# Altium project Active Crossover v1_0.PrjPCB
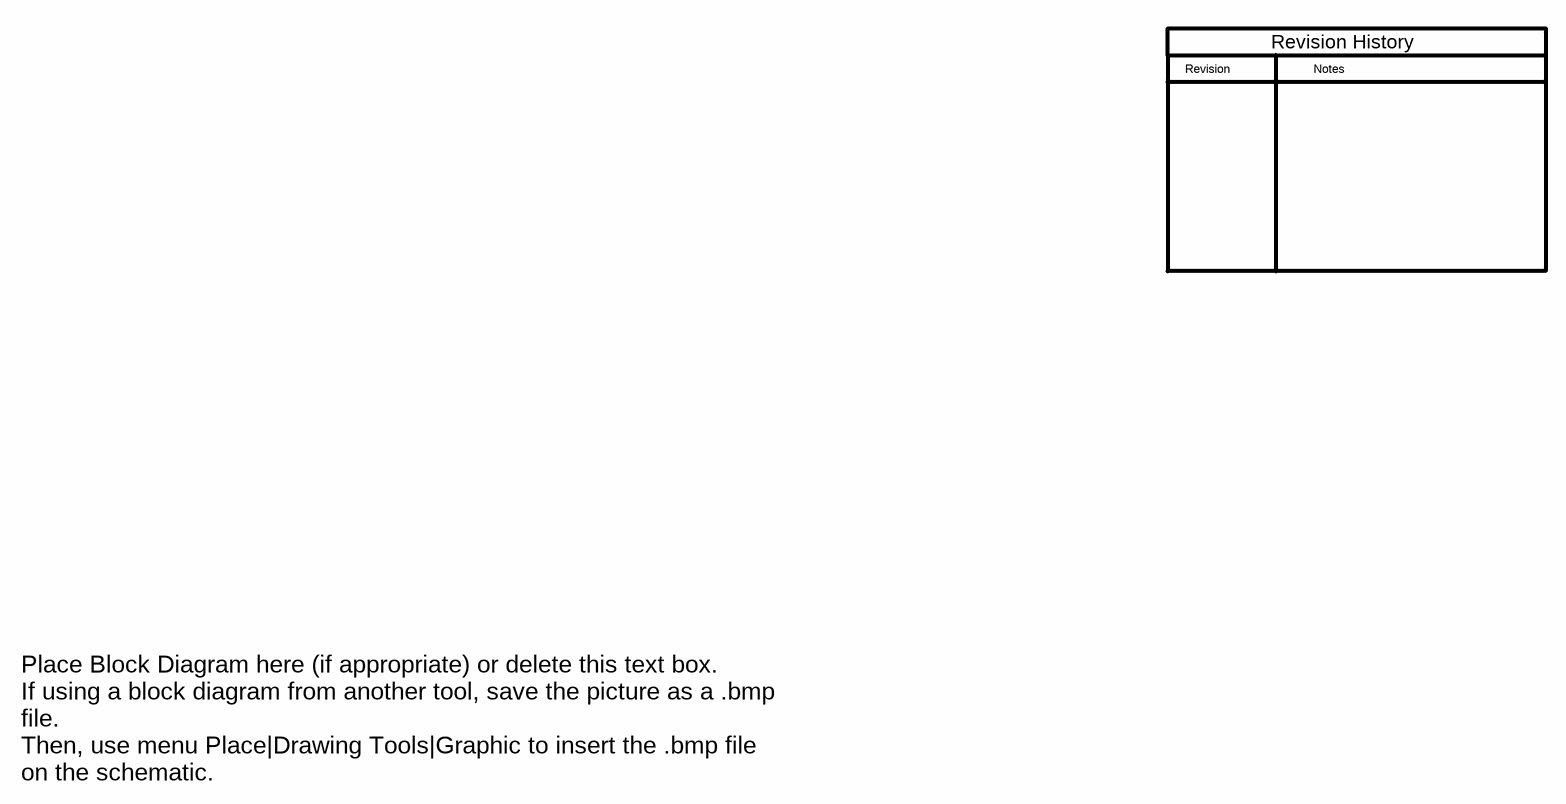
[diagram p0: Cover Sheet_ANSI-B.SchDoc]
TechSupport: http://www.ti.com/support; SCH_Rev: 1; PRJ_Title: Analog Active Loudspeaker Crossover; PRJ_Engineer: John Caldwell; PRJ_Customer: Public Release; PCB_Rev: 1; PCB_Layout: John Caldwell; CopyrightYear: 2013
2 sheets, 57 parts. Net scope: global (net labels, ports and power ports of the same name join across sheets).
Board file: Active Crossover v1_0.PcbDoc
Sheets:
  Cover Sheet_ANSI-B.SchDoc
  Schematic.SchDoc

## Sheet Cover Sheet_ANSI-B.SchDoc: ChangeMe
size 431 x 279 mm; Date: Not shown in title block; ApprovedBy: Not shown in title block; CheckedBy: Not shown in title block; Author: Not shown in title block; CompanyName: Not shown in title block; DrawnBy: Enter Full Name; Engineer: Not shown in title block; Organization: Not shown in title block; Address1: Not shown in title block; Address2: Not shown in title block; Address3: Not shown in title block; Address4: Not shown in title block; DocumentNumber: 1; Revision: Use project parameter SCH_Rev; SheetNumber: 1; SheetTotal: 3; PageSetup: Record=PageOptions|CenterHorizontal=True|CenterVertical=True|PrintScale=1.00|XCorrection=1.00|YCorrection=1.00|PrintKind=0|BorderSize=5000000|LeftOffset=0|BottomOffset=0|Orientation=2|PaperLength=1000|PaperWidth=1000|Scale=100|PaperSource=15|PrintQuality=600|MediaType=1|DitherType=10|PaperKind=Letter|PrintScaleMode=1

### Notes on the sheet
- Revision
- Notes
- Revision History
- Place Block Diagram here (if appropriate) or delete this text box.
  If using a block diagram from another tool, save the picture as a .bmp file.
  Then, use menu Place|Drawing Tools|Graphic to insert the .bmp file on the schematic.

## Sheet Schematic.SchDoc: ChangeMe
size 431 x 279 mm; Date: Not shown in title block; ApprovedBy: Not shown in title block; CheckedBy: Not shown in title block; Author: Not shown in title block; CompanyName: Not shown in title block; DrawnBy: Enter Full Name; Engineer: Not shown in title block; Organization: Not shown in title block; Address1: Not shown in title block; Address2: Not shown in title block; Address3: Not shown in title block; Address4: Not shown in title block; DocumentNumber: 2; Revision: Use project parameter SCH_Rev; SheetNumber: 2; SheetTotal: 3; PageSetup: Record=PageOptions|CenterHorizontal=True|CenterVertical=True|PrintScale=0.62|XCorrection=1.00|YCorrection=1.00|PrintKind=0|BorderSize=5000000|LeftOffset=0|BottomOffset=0|Orientation=2|PaperLength=1000|PaperWidth=1000|Scale=100|PaperSource=15|PrintQuality=600|MediaType=1|DitherType=10|PaperKind=Letter|PrintScaleMode=1
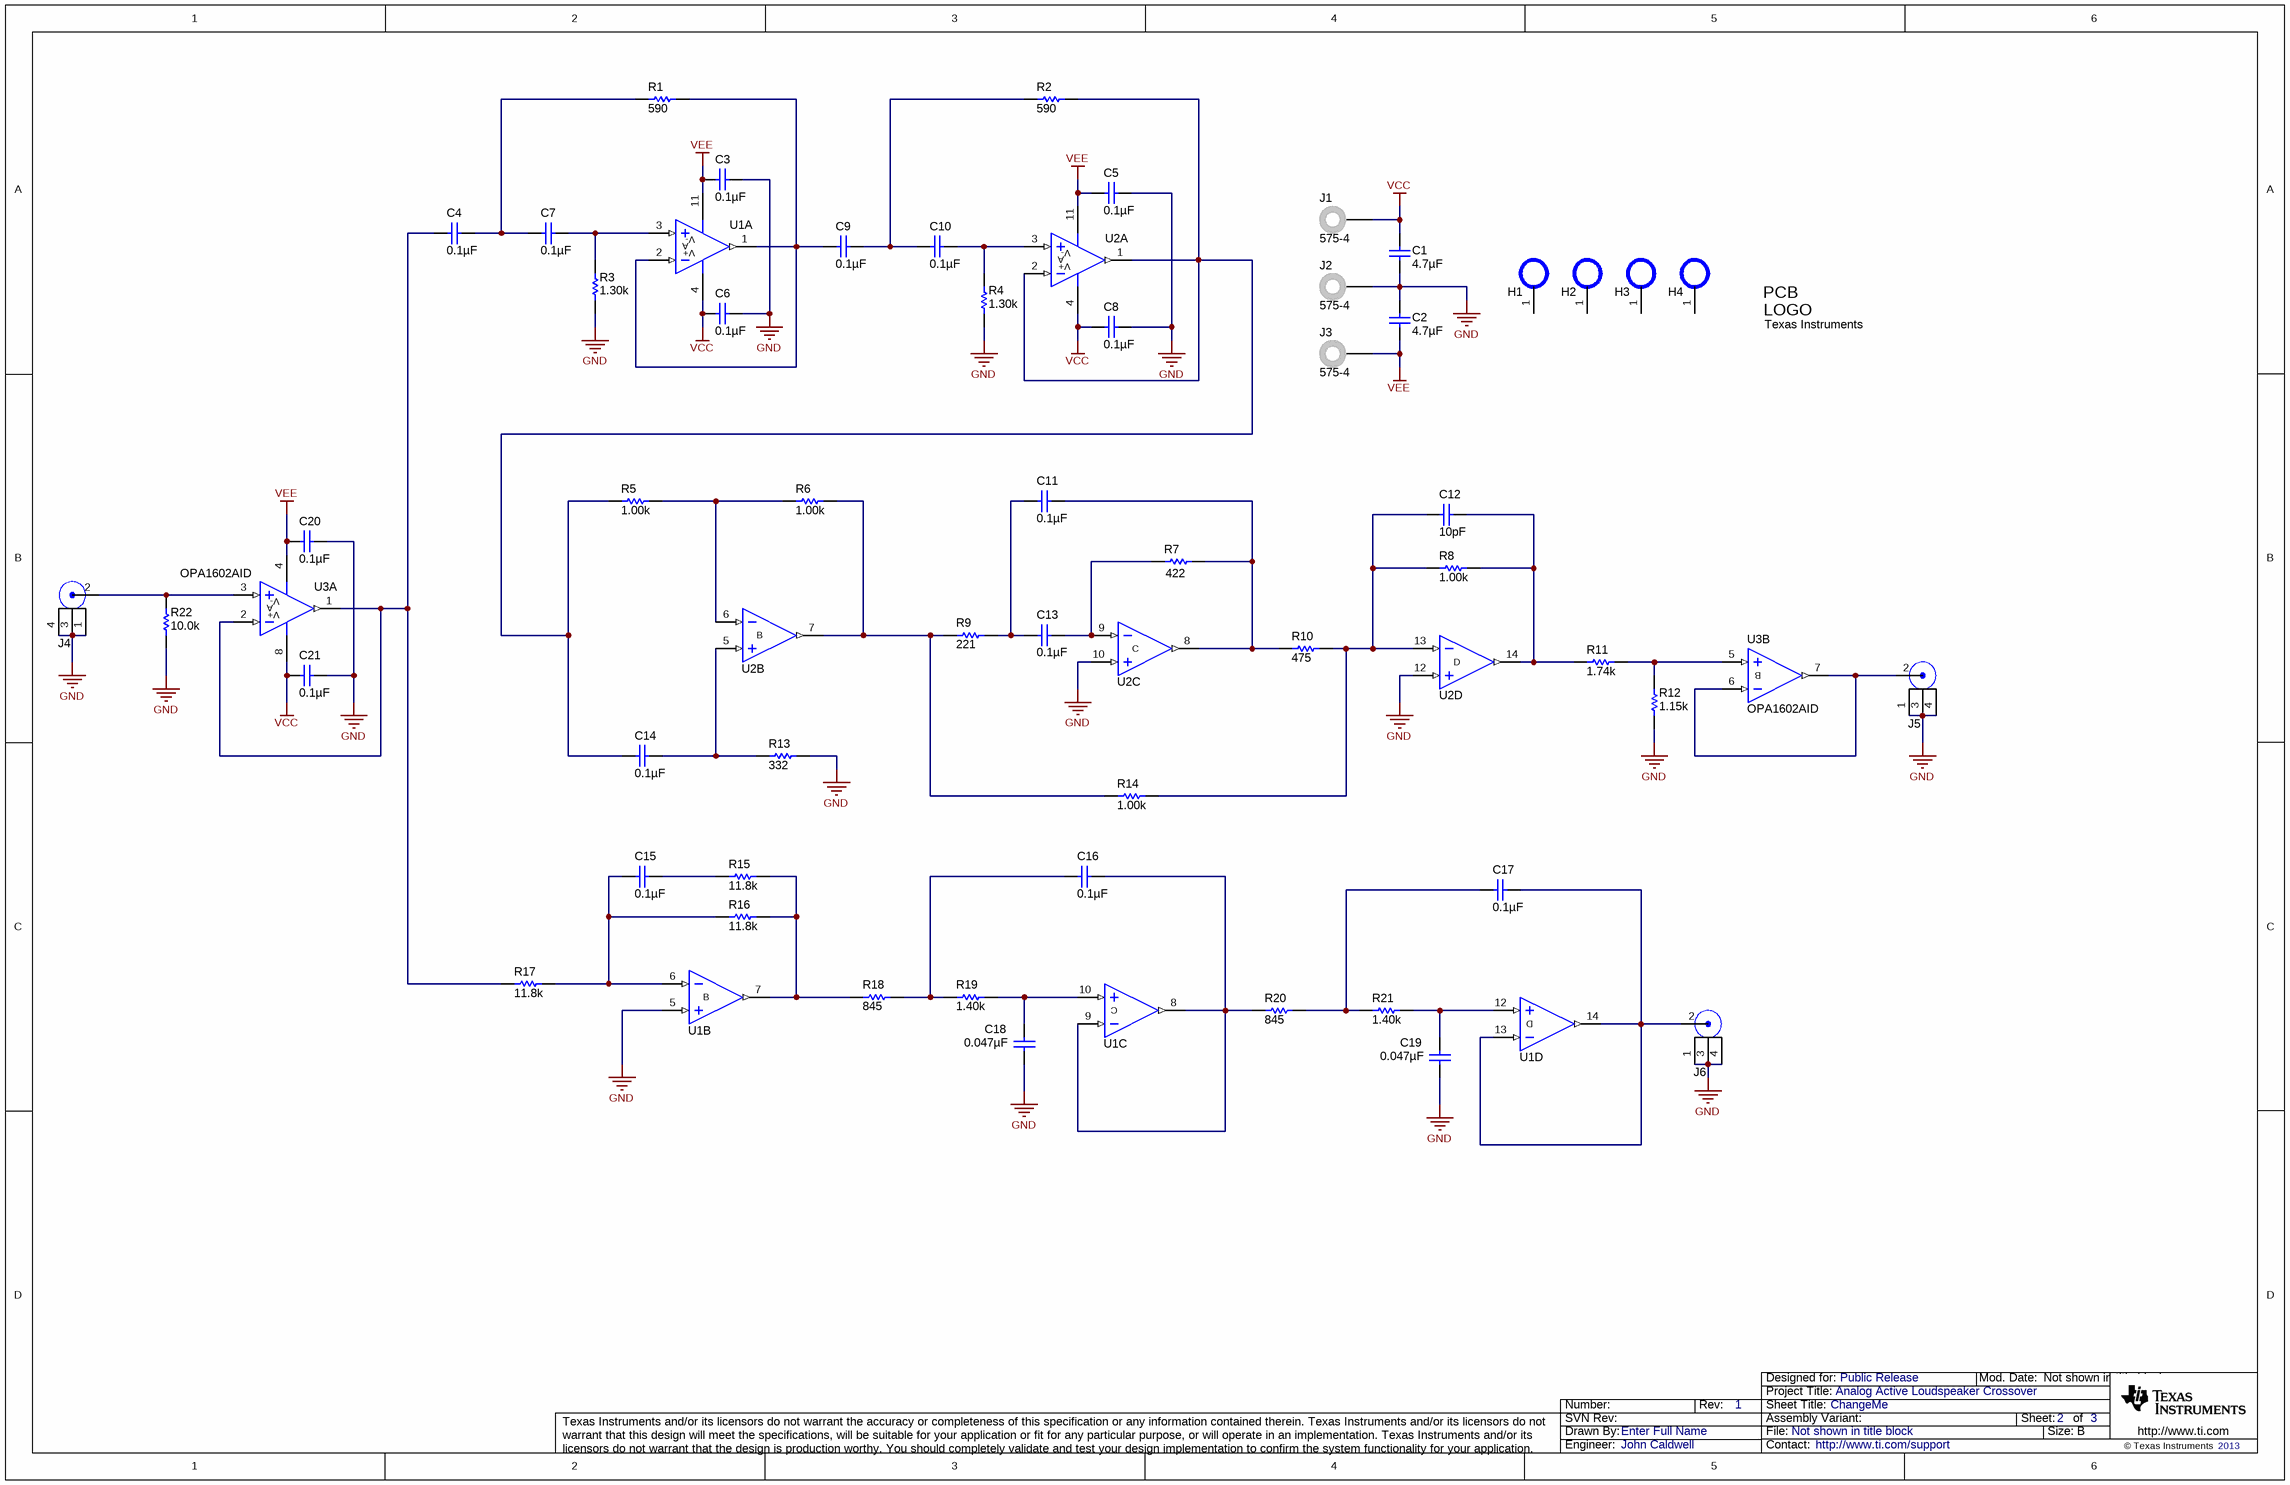
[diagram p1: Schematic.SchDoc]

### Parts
C1  ValueDisplayed: 4.7µF  [1206]  (hidden comment: C1206C475K4PACTU)
C2  ValueDisplayed: 4.7µF  [1206]  (hidden comment: C1206C475K4PACTU)
C3  ValueDisplayed: 0.1µF  [0603]  (hidden comment: 0603YC104JAT2A)
C4  ValueDisplayed: 0.1µF  [1206]  (hidden comment: C3216C0G1E104J)
C5  ValueDisplayed: 0.1µF  [0603]  (hidden comment: 0603YC104JAT2A)
C6  ValueDisplayed: 0.1µF  [0603]  (hidden comment: 0603YC104JAT2A)
C7  ValueDisplayed: 0.1µF  [1206]  (hidden comment: C3216C0G1E104J)
C8  ValueDisplayed: 0.1µF  [0603]  (hidden comment: 0603YC104JAT2A)
C9  ValueDisplayed: 0.1µF  [1206]  (hidden comment: C3216C0G1E104J)
C10  ValueDisplayed: 0.1µF  [1206]  (hidden comment: C3216C0G1E104J)
C11  ValueDisplayed: 0.1µF  [1206]  (hidden comment: C3216C0G1E104J)
C12  ValueDisplayed: 10pF  [0603]  (hidden comment: 06035A100JAT2A)
C13  ValueDisplayed: 0.1µF  [1206]  (hidden comment: C3216C0G1E104J)
C14  ValueDisplayed: 0.1µF  [1206]  (hidden comment: C3216C0G1E104J)
C15  ValueDisplayed: 0.1µF  [1206]  (hidden comment: C3216C0G1E104J)
C16  ValueDisplayed: 0.1µF  [1206]  (hidden comment: C3216C0G1E104J)
C17  ValueDisplayed: 0.1µF  [1206]  (hidden comment: C3216C0G1E104J)
C18  ValueDisplayed: 0.047µF  [1206]  (hidden comment: GRM31M5C1H473JA01L)
C19  ValueDisplayed: 0.047µF  [1206]  (hidden comment: GRM31M5C1H473JA01L)
C20  ValueDisplayed: 0.1µF  [0603]  (hidden comment: 0603YC104JAT2A)
C21  ValueDisplayed: 0.1µF  [0603]  (hidden comment: 0603YC104JAT2A)
H1  NA  [Mounting Hole]  (value not drawn)  (no BOM)
H2  NA  [Mounting Hole]  (value not drawn)  (no BOM)
H3  NA  [Mounting Hole]  (value not drawn)  (no BOM)
H4  NA  [Mounting Hole]  (value not drawn)  (no BOM)
J1  575-4  [Keystone_575-4]
J2  575-4  [Keystone_575-4]
J3  575-4  [Keystone_575-4]
J4  RCJ-011  [RCJ-01X]  (value not drawn)
J5  RCJ-011  [RCJ-01X]  (value not drawn)
J6  RCJ-011  [RCJ-01X]  (value not drawn)
Logo1  Texas Instruments  [TI_Stacked_Overlay_Small]  (no BOM)
R1  value 590  [1206]  (hidden comment: CRCW1206590RFKEA)
R2  value 590  [1206]  (hidden comment: CRCW1206590RFKEA)
R3  value 1.30k  [1206]  (hidden comment: CRCW12061K30FKEA)
R4  value 1.30k  [1206]  (hidden comment: CRCW12061K30FKEA)
R5  value 1.00k  [1206]  (hidden comment: CRCW12061K00FKEA)
R6  value 1.00k  [1206]  (hidden comment: CRCW12061K00FKEA)
R7  value 422  [1206]  (hidden comment: CRCW1206422RFKEA)
R8  value 1.00k  [1206]  (hidden comment: CRCW12061K00FKEA)
R9  value 221  [1206]  (hidden comment: CRCW1206221RFKEA)
R10  value 475  [1206]  (hidden comment: CRCW1206475RFKEA)
R11  value 1.74k  [1206]  (hidden comment: CRCW12061K74FKEA)
R12  value 1.15k  [1206]  (hidden comment: CRCW12061K15FKEA)
R13  value 332  [1206]  (hidden comment: CRCW1206332RFKEA)
R14  value 1.00k  [1206]  (hidden comment: CRCW12061K00FKEA)
R15  value 11.8k  [1206]  (hidden comment: CRCW120611K8FKEA)
R16  value 11.8k  [1206]  (hidden comment: CRCW120611K8FKEA)
R17  value 11.8k  [1206]  (hidden comment: CRCW120611K8FKEA)
R18  value 845  [1206]  (hidden comment: CRCW1206845RFKEA)
R19  value 1.40k  [1206]  (hidden comment: CRCW12061K40FKEA)
R20  value 845  [1206]  (hidden comment: CRCW1206845RFKEA)
R21  value 1.40k  [1206]  (hidden comment: CRCW12061K40FKEA)
R22  value 10.0k  [1206]  (hidden comment: CRCW120610K0FKEA)
U1  OPA1604AIDR  [D0014A_M]  (value not drawn)  (parts A,B,C,D of 4)
U2  OPA1604AIDR  [D0014A_M]  (value not drawn)  (parts A,B,C,D of 4)
U3  OPA1602AID  [D0008A_M]  (parts A,B of 2)

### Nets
GND: C1.2 C2.1 C3.1 C5.1 C6.1 C8.1 C18.2 C19.2 C20.1 C21.1 J2.1 J4.1 J4.3 J4.4 J5.1 J5.3 J5.4 J6.1 J6.3 J6.4 R3.1 R4.1 R12.1 R13.2 R22.1 U1.5(IN+) U2.10(IN+) U2.12(IN+)
VCC: C1.1 C6.2 C8.2 C21.2 J1.1 U1.4(V+) U2.4(V+) U3.8(V+)
VEE: C2.2 C3.2 C5.2 C20.2 J3.1 U1.11(V-) U2.11(V-) U3.4(V-)
NetC4_1: C4.1 C7.2 R1.1
NetC4_2: C4.2 R17.1 U3.1(OUT) U3.2(IN-)
NetC7_1: C7.1 R3.2 U1.3(IN+)
NetC9_1: C9.1 C10.2 R2.1
NetC9_2: C9.2 R1.2 U1.1(OUT) U1.2(IN-)
NetC10_1: C10.1 R4.2 U2.3(IN+)
NetC11_1: C11.1 R7.2 R10.1 U2.8(OUT)
NetC11_2: C11.2 C13.2 R9.2
NetC12_1: C12.1 R8.2 R11.1 U2.14(OUT)
NetC12_2: C12.2 R8.1 R10.2 R14.2 U2.13(IN-)
NetC13_1: C13.1 R7.1 U2.9(IN-)
NetC14_1: C14.1 R13.1 U2.5(IN+)
NetC14_2: C14.2 R2.2 R5.1 U2.1(OUT) U2.2(IN-)
NetC15_1: C15.1 R15.1
NetC15_2: C15.2 R16.1 R17.2 U1.6(IN-)
NetC16_1: C16.1 R20.1 U1.8(OUT) U1.9(IN-)
NetC16_2: C16.2 R18.2 R19.1
NetC17_1: C17.1 J6.2 U1.13(IN-) U1.14(OUT)
NetC17_2: C17.2 R20.2 R21.1
NetC18_1: C18.1 R19.2 U1.10(IN+)
NetC19_1: C19.1 R21.2 U1.12(IN+)
NetJ4_2: J4.2 R22.2 U3.3(IN+)
NetJ5_2: J5.2 U3.6(IN-) U3.7(OUT)
NetR5_2: R5.2 R6.1 U2.6(IN-)
NetR6_2: R6.2 R9.1 R14.1 U2.7(OUT)
NetR11_2: R11.2 R12.2 U3.5(IN+)
NetR15_2: R15.2 R16.2 R18.1 U1.7(OUT)

Not connected (* = marked no-connect by the designer): H1 1; H2 1; H3 1; H4 1

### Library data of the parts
C1 C2 = C1206C475K4PACTU: CAP, CERM, 4.7uF, 16V, +/-10%, X5R, 1206; Manufacturer: Kemet; Polarized: N; CompType: Capacitor; U/M: EA; Cap_F: 0.0000047; Tolerance_%: 10; ESR_Ohm: 0.013; Value1: 0.013 ohm; VDC_V: 16; IRMS_A: 4.9; TaMin_C: -55; TaMax_C: 85
C3 C5 C6 C8 C20 C21 = 0603YC104JAT2A: CAP, CERM, 0.1uF, 16V, +/-5%, X7R, 0603; Manufacturer: AVX; Polarized: N; CompType: Capacitor; U/M: EA; Cap_F: 0.0000001; Tolerance_%: 5; ESR_Ohm: 0.039; Value1: 0.039 ohm; VDC_V: 16; TaMin_C: -55; TaMax_C: 125
C4 C7 C9-C11 C13-C17 = C3216C0G1E104J: CAP, CERM, 0.1uF, 25V, +/-5%, C0G/NP0, 1206; Manufacturer: TDK; Polarized: N; CompType: Capacitor; U/M: EA; Cap_F: 0.0000001; Tolerance_%: 5; VDC_V: 25; TaMin_C: -55; TaMax_C: 125
C12 = 06035A100JAT2A: CAP, CERM, 10pF, 50V, +/-5%, C0G/NP0, 0603; Manufacturer: AVX; Polarized: N; CompType: Capacitor; U/M: EA; Cap_F: 0.00000000001; Tolerance_%: 5; ESR_Ohm: 0.403; Value1: 0.403 ohm; VDC_V: 50; TaMin_C: -55; TaMax_C: 125
C18 C19 = GRM31M5C1H473JA01L: CAP, CERM, 0.047uF, 50V, +/-5%, C0G/NP0, 1206; Manufacturer: MuRata; Polarized: N; CompType: Capacitor; U/M: EA; Cap_F: 0.000000047; Tolerance_%: 5; VDC_V: 50; TaMin_C: -55; TaMax_C: 125
H1-H4 = Mounting Hole: Manufacturer: Used in BOM report; SymbolVersion: use current date i.e. 2008-05-20; SymbolCreator: Use LDAP id; CompType: Used in some BOM reports.  Useful for finding later.; U/M: EA, IN, or GM
J1-J3 = 575-4: Standard Banana Jack, Uninsulated, 5.5mm; Manufacturer: Keystone; Alternate Manufacturer: Any; Alternate PartNumber: Equivalent; CompType: Connector; U/M: EA
J4-J6 = RCJ-011: RCA Jack, Metal, Right Angle; Manufacturer: CUI Inc; SymbolVersion: use current date i.e. 2008-05-20; SymbolCreator: Use LDAP id; CompType: Used in some BOM reports.  Useful for finding later.; U/M: EA, IN, or GM
Logo1 = TI_Logo: Texas Instrument Corporate Signature; SymbolCreator: codlsc
R1 R2 = CRCW1206590RFKEA: RES, 590 ohm, 1%, 0.25W, 1206; Manufacturer: Vishay-Dale; Alternate Manufacturer: Any; Alternate PartNumber: Equivalent; CompType: Resistor; Value_Code: 590R; Tolerance_%: 1; Power_W: 0.25; VDC_V: 200; TempCo: 100 ppm/C; EIA_Code: E96; U/M: EA
R3 R4 = CRCW12061K30FKEA: RES, 1.30k ohm, 1%, 0.25W, 1206; Manufacturer: Vishay-Dale; Alternate Manufacturer: Any; Alternate PartNumber: Equivalent; CompType: Resistor; Res_ohm: 1300; Value_Code: 1k30; Tolerance_%: 1; Power_W: 0.25; VDC_V: 200; TempCo: 100 ppm/C; EIA_Code: E96; U/M: EA
R5 R6 R8 R14 = CRCW12061K00FKEA: RES, 1.00k ohm, 1%, 0.25W, 1206; Manufacturer: Vishay-Dale; Alternate Manufacturer: Any; Alternate PartNumber: Equivalent; CompType: Resistor; Res_ohm: 1000; Value_Code: 1k00; Tolerance_%: 1; Power_W: 0.25; VDC_V: 200; TempCo: 100 ppm/C; EIA_Code: E96; U/M: EA
R7 = CRCW1206422RFKEA: RES, 422 ohm, 1%, 0.25W, 1206; Manufacturer: Vishay-Dale; Alternate Manufacturer: Any; Alternate PartNumber: Equivalent; CompType: Resistor; Value_Code: 422R; Tolerance_%: 1; Power_W: 0.25; VDC_V: 200; TempCo: 100 ppm/C; EIA_Code: E96; U/M: EA
R9 = CRCW1206221RFKEA: RES, 221 ohm, 1%, 0.25W, 1206; Manufacturer: Vishay-Dale; Alternate Manufacturer: Any; Alternate PartNumber: Equivalent; CompType: Resistor; Value_Code: 221R; Tolerance_%: 1; Power_W: 0.25; VDC_V: 200; TempCo: 100 ppm/C; EIA_Code: E96; U/M: EA
R10 = CRCW1206475RFKEA: RES, 475 ohm, 1%, 0.25W, 1206; Manufacturer: Vishay-Dale; Alternate Manufacturer: Any; Alternate PartNumber: Equivalent; CompType: Resistor; Value_Code: 475R; Tolerance_%: 1; Power_W: 0.25; VDC_V: 200; TempCo: 100 ppm/C; EIA_Code: E96; U/M: EA
R11 = CRCW12061K74FKEA: RES, 1.74k ohm, 1%, 0.25W, 1206; Manufacturer: Vishay-Dale; Alternate Manufacturer: Any; Alternate PartNumber: Equivalent; CompType: Resistor; Res_ohm: 1740; Value_Code: 1k74; Tolerance_%: 1; Power_W: 0.25; VDC_V: 200; TempCo: 100 ppm/C; EIA_Code: E96; U/M: EA
R12 = CRCW12061K15FKEA: RES, 1.15k ohm, 1%, 0.25W, 1206; Manufacturer: Vishay-Dale; Alternate Manufacturer: Any; Alternate PartNumber: Equivalent; CompType: Resistor; Res_ohm: 1150; Value_Code: 1k15; Tolerance_%: 1; Power_W: 0.25; VDC_V: 200; TempCo: 100 ppm/C; EIA_Code: E96; U/M: EA
R13 = CRCW1206332RFKEA: RES, 332 ohm, 1%, 0.25W, 1206; Manufacturer: Vishay-Dale; Alternate Manufacturer: Any; Alternate PartNumber: Equivalent; CompType: Resistor; Value_Code: 332R; Tolerance_%: 1; Power_W: 0.25; VDC_V: 200; TempCo: 100 ppm/C; EIA_Code: E96; U/M: EA
R15-R17 = CRCW120611K8FKEA: RES, 11.8k ohm, 1%, 0.25W, 1206; Manufacturer: Vishay-Dale; Alternate Manufacturer: Any; Alternate PartNumber: Equivalent; CompType: Resistor; Res_ohm: 11800; Value_Code: 11k8; Tolerance_%: 1; Power_W: 0.25; VDC_V: 200; TempCo: 100 ppm/C; EIA_Code: E96; U/M: EA
R18 R20 = CRCW1206845RFKEA: RES, 845 ohm, 1%, 0.25W, 1206; Manufacturer: Vishay-Dale; Alternate Manufacturer: Any; Alternate PartNumber: Equivalent; CompType: Resistor; Value_Code: 845R; Tolerance_%: 1; Power_W: 0.25; VDC_V: 200; TempCo: 100 ppm/C; EIA_Code: E96; U/M: EA
R19 R21 = CRCW12061K40FKEA: RES, 1.40k ohm, 1%, 0.25W, 1206; Manufacturer: Vishay-Dale; Alternate Manufacturer: Any; Alternate PartNumber: Equivalent; CompType: Resistor; Res_ohm: 1400; Value_Code: 1k40; Tolerance_%: 1; Power_W: 0.25; VDC_V: 200; TempCo: 100 ppm/C; EIA_Code: E96; U/M: EA
R22 = CRCW120610K0FKEA: RES, 10.0k ohm, 1%, 0.25W, 1206; Manufacturer: Vishay-Dale; Alternate Manufacturer: Any; Alternate PartNumber: Equivalent; CompType: Resistor; Res_ohm: 10000; Value_Code: 10k0; Tolerance_%: 1; Power_W: 0.25; VDC_V: 200; TempCo: 100 ppm/C; EIA_Code: E96; U/M: EA
U1 U2 = OPA1604: Quad, Low Noise, Audio Operational Amplifier; Manufacturer: Texas Instruments; SymbolVersion: use current date i.e. 2008-05-20; SymbolCreator: Use LDAP id; CompType: Op Amp; U/M: EA, IN, or GM
U3 = OPA1602: Dual, Low Noise, Audio Operational Amplifier; Manufacturer: Texas Instruments; SymbolVersion: use current date i.e. 2008-05-20; SymbolCreator: Use LDAP id; CompType: Used in some BOM reports.  Useful for finding later.; U/M: EA, IN, or GM

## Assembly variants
001: all parts fitted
